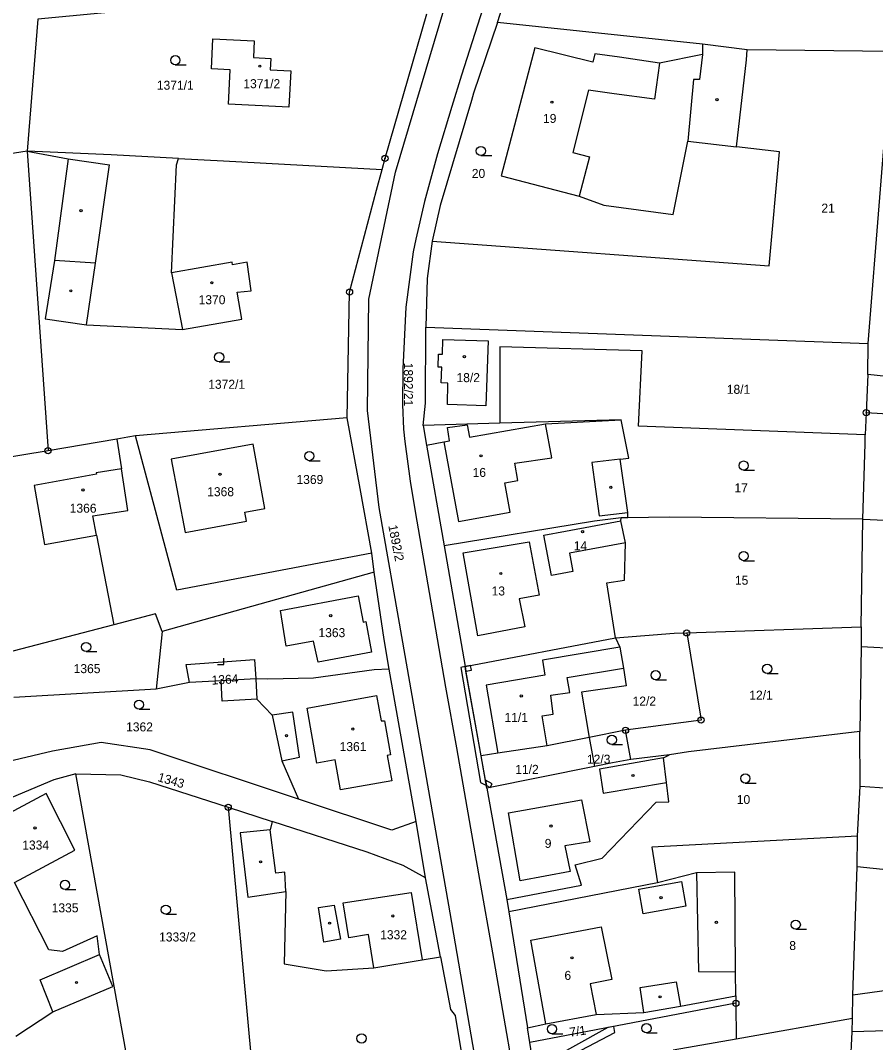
# Model space of a CAD drawing. Extents: x -587171 to -555306, y -1167727 to -1074732.
# Drawn here: x -559747.3 to -559608.7, y -1076385.1 to -1076219.5 of the extents above; entities that cross this region are included whole.
import ezdxf

# ---------------------------------------------------------------- set-up
doc = ezdxf.new("R2010")
doc.units = 0
for name, color, linetype in [('Hranice parcel', 7, 'Continuous'), ('Parcelní čísla', 7, 'Continuous'), ('Vnitřní kresba', 7, 'Continuous'), ('Věcná břemena k části', 7, 'Continuous'), ('Značky bodu BP', 7, 'Continuous'), ('Značky budov', 7, 'Continuous'), ('Značky kultur', 7, 'Continuous')]:
    doc.layers.add(name, color=color, linetype=linetype)

msp = doc.modelspace()

# ---------------------------------------------------------------- linework, layer by layer
at = {"layer": 'Hranice parcel'}
for p, q in [((-559669.97, -1076219.81), (-559666.56, -1076209.16)), ((-559688.2, -1076241.83), (-559681.43, -1076218.42)), ((-559636.74, -1076223.34), (-559669.97, -1076219.81)), ((-559629.52, -1076224.24), (-559636.74, -1076223.34)), ((-559606.11, -1076224.52), (-559629.52, -1076224.24)), ((-559609.89, -1076271.82), (-559606.11, -1076224.52)), ((-559746.19, -1076240.66), (-559774.92, -1076245.29)), ((-559746.19, -1076240.66), (-559742.81, -1076289.2)), ((-559721.97, -1076242.88), (-559721.67, -1076241.85)), ((-559688.69, -1076243.66), (-559688.2, -1076241.83)), ((-559689.57, -1076246.99), (-559688.69, -1076243.66)), ((-559681.61, -1076269.19), (-559609.89, -1076271.82)), ((-559609.99, -1076276.84), (-559609.89, -1076271.82)), ((-559609.99, -1076276.84), (-559610.23, -1076283.04)), ((-559524.17, -1076286.21), (-559609.99, -1076276.84)), ((-559610.23, -1076283.04), (-559610.37, -1076286.62)), ((-559525.24, -1076288.45), (-559610.23, -1076283.04)), ((-559694.32, -1076283.88), (-559728.64, -1076286.81)), ((-559669.62, -1076284.73), (-559682.03, -1076285.09)), ((-559731.68, -1076287.32), (-559742.81, -1076289.2)), ((-559742.81, -1076289.2), (-559761.21, -1076292.32)), ((-559649.97, -1076300.57), (-559649.96, -1076300.08)), ((-559648.87, -1076300.06), (-559649.96, -1076300.08)), ((-559649.22, -1076304.13), (-559649.97, -1076300.57)), ((-559611.07, -1076317.75), (-559610.75, -1076300.3)), ((-559610.75, -1076300.3), (-559532.59, -1076303.73)), ((-559678.62, -1076304.6), (-559675.24, -1076324.16)), ((-559689.97, -1076308.89), (-559690.36, -1076305.79)), ((-559689.97, -1076308.89), (-559724.34, -1076318.46)), ((-559732.13, -1076317.38), (-559751.67, -1076322.49)), ((-559639.31, -1076318.71), (-559611.07, -1076317.75)), ((-559611.07, -1076317.75), (-559611.03, -1076320.97)), ((-559724.34, -1076318.46), (-559725.3, -1076327.83)), ((-559675.24, -1076324.16), (-559650.83, -1076319.51)), ((-559611.03, -1076320.97), (-559611.27, -1076334.66)), ((-559542.75, -1076324.48), (-559611.03, -1076320.97)), ((-559683.14, -1076349.27), (-559687.53, -1076324.57)), ((-559672.64, -1076338.64), (-559675.24, -1076324.16)), ((-559725.3, -1076327.83), (-559748.34, -1076329.2)), ((-559719.91, -1076326.76), (-559725.3, -1076327.83)), ((-559649.23, -1076334.49), (-559655.1, -1076335.65)), ((-559648.37, -1076339.21), (-559649.23, -1076334.49)), ((-559611.22, -1076343.53), (-559611.27, -1076334.66)), ((-559655.1, -1076335.65), (-559654.28, -1076340.35)), ((-559671.7, -1076343.88), (-559672.64, -1076338.64)), ((-559642.13, -1076338.47), (-559648.37, -1076339.21)), ((-559730.08, -1076387.01), (-559738.33, -1076341.52)), ((-559654.28, -1076340.35), (-559671.7, -1076343.88)), ((-559671.7, -1076343.88), (-559668.49, -1076361.9)), ((-559611.62, -1076351.63), (-559611.22, -1076343.53)), ((-559611.22, -1076343.53), (-559553.95, -1076347.35)), ((-559713.61, -1076346.96), (-559709.16, -1076395.49)), ((-559713.61, -1076346.96), (-559706.47, -1076349.27)), ((-559681.64, -1076358.38), (-559683.14, -1076349.27)), ((-559611.68, -1076356.63), (-559611.62, -1076351.63)), ((-559612.37, -1076377.39), (-559611.68, -1076356.63)), ((-559596.39, -1076358.13), (-559611.68, -1076356.63)), ((-559679.2, -1076371.2), (-559681.64, -1076358.38)), ((-559644.06, -1076359.22), (-559668.13, -1076363.91)), ((-559668.49, -1076361.9), (-559668.13, -1076363.91)), ((-559668.13, -1076363.91), (-559665.12, -1076382.68)), ((-559682.16, -1076371.7), (-559679.2, -1076371.2)), ((-559600.56, -1076375.8), (-559612.37, -1076377.39)), ((-559631.36, -1076377.5), (-559631.35, -1076378.72)), ((-559612.46, -1076381.18), (-559612.37, -1076377.39)), ((-559631.35, -1076378.72), (-559664.74, -1076385.04)), ((-559631.35, -1076378.72), (-559631.29, -1076384.51)), ((-559612.46, -1076381.18), (-559631.29, -1076384.51)), ((-559612.51, -1076383.33), (-559612.46, -1076381.18)), ((-559664.74, -1076385.04), (-559665.12, -1076382.68)), ((-559631.29, -1076384.51), (-559641.49, -1076386.31)), ((-559613.69, -1076407.52), (-559612.51, -1076383.33)), ((-559602.27, -1076383.08), (-559612.51, -1076383.33)), ((-559663.9, -1076390.27), (-559664.74, -1076385.04))]:
    msp.add_line(p, q, dxfattribs=at)
for points in [[(-559670.6, -1076212.13), (-559675.79, -1076228.36), (-559677.4, -1076233.42), (-559679.72, -1076241.09), (-559681.8, -1076248.81), (-559683.23, -1076254.95), (-559683.64, -1076256.99), (-559684.85, -1076265.92), (-559685.34, -1076275.96), (-559685.36, -1076281.72), (-559685.2, -1076285.73), (-559685.01, -1076287.72), (-559684.15, -1076294.13), (-559683.32, -1076299.07), (-559680, -1076318.08), (-559678.38, -1076327.51), (-559676.63, -1076337.35), (-559674.34, -1076350.35), (-559672.89, -1076358.68), (-559670.79, -1076370.56), (-559668.73, -1076382.34), (-559667.79, -1076387.64)], [(-559723.95, -1076217.33), (-559744.45, -1076219.3), (-559746.19, -1076240.66)], [(-559669.97, -1076219.81), (-559673.87, -1076231.26), (-559674.19, -1076232.44), (-559679.29, -1076249.47), (-559680.58, -1076255.26)], [(-559716.34, -1076227.34), (-559716.09, -1076222.46), (-559709.41, -1076222.81), (-559709.54, -1076225.52), (-559706.72, -1076225.66), (-559706.8, -1076227.47), (-559703.48, -1076227.64), (-559703.77, -1076233.57), (-559713.58, -1076233.06), (-559713.29, -1076227.5), (-559716.34, -1076227.34)], [(-559636.74, -1076223.34), (-559636.74, -1076225.03), (-559643.7, -1076226.39), (-559650.23, -1076225.46), (-559654.21, -1076224.89), (-559654.53, -1076226.23), (-559663.93, -1076223.92), (-559669.38, -1076244.67), (-559656.76, -1076247.97), (-559652.74, -1076249.42), (-559641.52, -1076250.94), (-559639.14, -1076239.07), (-559631.27, -1076239.97)], [(-559631.27, -1076239.97), (-559629.65, -1076225.88), (-559629.52, -1076224.24)], [(-559680.58, -1076255.26), (-559625.94, -1076259.26), (-559624.26, -1076240.77), (-559631.27, -1076239.97)], [(-559721.67, -1076241.85), (-559732.61, -1076241.25), (-559746.19, -1076240.66)], [(-559746.19, -1076240.66), (-559739.57, -1076241.9), (-559741.74, -1076258.38), (-559743.29, -1076267.85), (-559736.59, -1076268.78), (-559721.03, -1076269.54), (-559711.4, -1076267.91), (-559712.16, -1076263.53), (-559709.91, -1076263.3), (-559710.52, -1076258.68), (-559712.92, -1076259.1), (-559713, -1076258.66), (-559722.83, -1076260.38), (-559721.97, -1076242.88)], [(-559721.67, -1076241.85), (-559714.39, -1076242.25), (-559688.69, -1076243.66)], [(-559694.32, -1076283.88), (-559693.95, -1076263.51), (-559689.57, -1076246.99)], [(-559680.58, -1076255.26), (-559681.38, -1076261.32), (-559681.61, -1076269.19)], [(-559682.03, -1076285.09), (-559681.62, -1076281.5), (-559681.61, -1076269.19)], [(-559678.83, -1076271.16), (-559671.5, -1076271.41), (-559671.86, -1076281.94), (-559678.09, -1076281.71), (-559678.01, -1076278.24), (-559679.09, -1076278.19), (-559679.01, -1076275.67), (-559679.6, -1076275.64), (-559679.52, -1076273.54), (-559678.91, -1076273.56), (-559678.83, -1076271.16)], [(-559610.37, -1076286.62), (-559647.15, -1076285.23), (-559646.51, -1076273.04), (-559669.61, -1076272.38), (-559669.62, -1076284.73)], [(-559690.36, -1076305.79), (-559692.23, -1076295.31), (-559694.32, -1076283.88)], [(-559682.03, -1076285.09), (-559681.46, -1076288.31), (-559678.62, -1076304.6)], [(-559648.87, -1076300.06), (-559648.87, -1076299.21), (-559650.12, -1076290.59), (-559648.68, -1076290.43), (-559649.02, -1076288.76), (-559649.93, -1076284.17), (-559669.62, -1076284.73)], [(-559728.64, -1076286.81), (-559729.87, -1076287), (-559731.68, -1076287.32)], [(-559690.36, -1076305.79), (-559721.93, -1076311.8), (-559728.64, -1076286.81)], [(-559610.75, -1076300.3), (-559610.42, -1076288.01), (-559610.37, -1076286.62)], [(-559731.68, -1076287.32), (-559730.93, -1076292.12), (-559735.02, -1076292.76), (-559734.98, -1076293.02), (-559745.06, -1076294.85), (-559743.38, -1076304.37), (-559734.96, -1076302.86), (-559732.13, -1076317.38)], [(-559720.57, -1076302.43), (-559710.66, -1076300.61), (-559710.93, -1076299.17), (-559707.66, -1076298.56), (-559709.55, -1076288.14), (-559722.85, -1076290.57), (-559720.57, -1076302.43)], [(-559649.96, -1076300.08), (-559654.24, -1076300.62), (-559678.62, -1076304.6)], [(-559610.75, -1076300.3), (-559642.18, -1076299.97), (-559648.87, -1076300.06)], [(-559649.22, -1076304.13), (-559658.29, -1076305.82), (-559657.75, -1076308.74), (-559661.2, -1076309.4), (-559662.45, -1076302.87), (-559658.98, -1076302.23), (-559649.97, -1076300.57)], [(-559650.83, -1076319.51), (-559652.28, -1076310.6), (-559649.4, -1076310.19), (-559649.22, -1076304.13)], [(-559687.53, -1076324.57), (-559688.36, -1076319.79), (-559689.97, -1076308.89)], [(-559724.34, -1076318.46), (-559725.39, -1076315.62), (-559732.13, -1076317.38)], [(-559650.83, -1076319.51), (-559650.17, -1076321.02), (-559649.56, -1076324.43), (-559649.1, -1076327.27), (-559656.38, -1076328.32), (-559655.1, -1076335.65)], [(-559650.83, -1076319.51), (-559641.35, -1076318.78), (-559639.31, -1076318.71)], [(-559639.31, -1076318.71), (-559636.99, -1076332.84), (-559649.23, -1076334.49)], [(-559719.91, -1076326.76), (-559720.42, -1076323.83), (-559709.34, -1076323.02), (-559709.14, -1076326.13)], [(-559687.53, -1076324.57), (-559689.95, -1076324.68), (-559699.8, -1076326.03), (-559707.17, -1076326.23), (-559709.14, -1076326.13)], [(-559709.14, -1076326.13), (-559714.77, -1076326.46), (-559719.91, -1076326.76)], [(-559709.14, -1076326.13), (-559708.97, -1076329.46), (-559706.49, -1076332.05), (-559704.95, -1076339.45), (-559702.24, -1076345.64)], [(-559611.27, -1076334.66), (-559639.03, -1076338), (-559642.13, -1076338.47)], [(-559702.24, -1076345.64), (-559726.29, -1076337.65), (-559734.22, -1076336.48), (-559742.09, -1076337.88), (-559756.94, -1076341.36)], [(-559655.1, -1076335.65), (-559661.91, -1076336.99), (-559669.91, -1076338.22), (-559672.64, -1076338.64)], [(-559668.49, -1076361.9), (-559656.38, -1076359.57), (-559657.4, -1076356.26), (-559653.02, -1076355.2), (-559644.24, -1076346.15), (-559642.23, -1076346.06), (-559642.58, -1076342.93), (-559643.05, -1076338.96), (-559642.13, -1076338.47)], [(-559648.37, -1076339.21), (-559651.34, -1076339.75), (-559654.28, -1076340.35)], [(-559738.33, -1076341.52), (-559741.88, -1076342.53), (-559751.79, -1076346.69)], [(-559738.33, -1076341.52), (-559731, -1076341.7), (-559726.37, -1076342.84), (-559713.61, -1076346.96)], [(-559748.02, -1076384.02), (-559742.01, -1076380.08), (-559732.34, -1076376.02), (-559734.46, -1076370.82), (-559734.83, -1076367.76), (-559740.49, -1076370.33), (-559742.68, -1076370.04), (-559748.24, -1076359.12), (-559738.45, -1076353.89), (-559743.09, -1076344.75), (-559750.71, -1076348.8), (-559751.79, -1076346.69)], [(-559683.14, -1076349.27), (-559687.08, -1076350.67), (-559702.24, -1076345.64)], [(-559706.47, -1076349.27), (-559706.8, -1076350.6), (-559711.66, -1076351.09)], [(-559681.64, -1076358.38), (-559685.26, -1076356.4), (-559691.1, -1076354.24), (-559706.47, -1076349.27)], [(-559711.66, -1076351.09), (-559710.45, -1076361.5), (-559704.29, -1076360.62)], [(-559611.62, -1076351.63), (-559644.95, -1076353.42), (-559644.06, -1076359.22)], [(-559631.36, -1076377.5), (-559631.39, -1076373.61), (-559631.53, -1076357.46), (-559637.72, -1076357.58), (-559644.06, -1076359.22)], [(-559704.29, -1076360.62), (-559704.53, -1076372.32), (-559697.73, -1076373.48)], [(-559679.2, -1076371.2), (-559677.59, -1076379.71), (-559676.86, -1076380.7), (-559670.93, -1076416.16)], [(-559697.73, -1076373.48), (-559690.04, -1076372.95), (-559682.16, -1076371.7)], [(-559665.12, -1076382.68), (-559662.15, -1076382.05), (-559653.99, -1076380.52), (-559646.25, -1076380.23), (-559640.34, -1076379.18), (-559631.36, -1076377.5)]]:
    msp.add_lwpolyline(points, dxfattribs=at)
at = {"layer": 'Vnitřní kresba'}
for p, q in [((-559686.52, -1076244.08), (-559676.92, -1076211.76)), ((-559636.74, -1076225.03), (-559637.26, -1076229.06)), ((-559643.7, -1076226.39), (-559644.51, -1076232.27)), ((-559638.23, -1076229.04), (-559639.14, -1076239.07)), ((-559637.26, -1076229.06), (-559638.23, -1076229.04)), ((-559655.24, -1076230.81), (-559657.76, -1076240.87)), ((-559651.08, -1076231.38), (-559655.24, -1076230.81)), ((-559644.51, -1076232.27), (-559651.08, -1076231.38)), ((-559739.57, -1076241.9), (-559732.83, -1076242.88)), ((-559657.76, -1076240.87), (-559655.08, -1076241.57)), ((-559655.08, -1076241.57), (-559656.76, -1076247.97)), ((-559735.14, -1076258.8), (-559732.83, -1076242.88)), ((-559690.81, -1076264.65), (-559686.52, -1076244.08)), ((-559735.14, -1076258.8), (-559741.74, -1076258.38)), ((-559736.59, -1076268.78), (-559735.14, -1076258.8)), ((-559722.83, -1076260.38), (-559721.03, -1076269.54)), ((-559691.06, -1076282.71), (-559690.81, -1076264.65)), ((-559689.16, -1076298.39), (-559691.06, -1076282.71)), ((-559678.09, -1076285.43), (-559674.87, -1076284.99)), ((-559674.87, -1076284.99), (-559674.51, -1076287.02)), ((-559674.51, -1076287.02), (-559662.21, -1076284.85)), ((-559662.21, -1076284.85), (-559649.93, -1076284.17)), ((-559661.16, -1076290.35), (-559662.21, -1076284.85)), ((-559677.78, -1076287.6), (-559678.09, -1076285.43)), ((-559681.46, -1076288.31), (-559678.67, -1076287.76)), ((-559678.67, -1076287.76), (-559677.78, -1076287.6)), ((-559678.67, -1076287.76), (-559676.28, -1076300.67)), ((-559667.19, -1076291.23), (-559661.16, -1076290.35)), ((-559666.7, -1076294.03), (-559667.19, -1076291.23)), ((-559650.12, -1076290.59), (-559654.7, -1076291.12)), ((-559654.7, -1076291.12), (-559653.51, -1076299.74)), ((-559729.87, -1076298.86), (-559730.93, -1076292.12)), ((-559668.79, -1076294.4), (-559666.7, -1076294.03)), ((-559667.93, -1076299.16), (-559668.79, -1076294.4)), ((-559685.31, -1076320.23), (-559689.16, -1076298.39)), ((-559735.58, -1076299.72), (-559729.87, -1076298.86)), ((-559734.96, -1076302.86), (-559735.58, -1076299.72)), ((-559676.28, -1076300.67), (-559667.93, -1076299.16)), ((-559653.51, -1076299.74), (-559648.87, -1076299.21)), ((-559675.52, -1076305.73), (-559664.83, -1076303.97)), ((-559664.83, -1076303.97), (-559663.21, -1076312.62)), ((-559673.18, -1076319.17), (-559675.52, -1076305.73)), ((-559705.14, -1076315.06), (-559692.55, -1076312.71)), ((-559692.55, -1076312.71), (-559691.77, -1076316.96)), ((-559663.21, -1076312.62), (-559666.44, -1076313.19)), ((-559666.44, -1076313.19), (-559665.54, -1076317.72)), ((-559704.24, -1076320.86), (-559705.14, -1076315.06)), ((-559691.77, -1076316.96), (-559691.29, -1076316.87)), ((-559691.29, -1076316.87), (-559690.38, -1076321.83)), ((-559665.54, -1076317.72), (-559673.18, -1076319.17)), ((-559699.79, -1076320.06), (-559704.24, -1076320.86)), ((-559699.05, -1076323.46), (-559699.79, -1076320.06)), ((-559677.67, -1076364.08), (-559685.31, -1076320.23)), ((-559650.17, -1076321.02), (-559662.66, -1076323.12)), ((-559690.38, -1076321.83), (-559699.05, -1076323.46)), ((-559662.66, -1076323.12), (-559662.32, -1076325.56)), ((-559658.67, -1076325.91), (-559649.56, -1076324.43)), ((-559714.57, -1076329.77), (-559714.77, -1076326.46)), ((-559662.32, -1076325.56), (-559671.79, -1076327.18)), ((-559658.28, -1076328.39), (-559658.67, -1076325.91)), ((-559671.79, -1076327.18), (-559669.91, -1076338.22)), ((-559708.97, -1076329.46), (-559714.57, -1076329.77)), ((-559700.81, -1076330.9), (-559689.57, -1076328.85)), ((-559689.57, -1076328.85), (-559688.84, -1076332.97)), ((-559661.35, -1076328.8), (-559658.28, -1076328.39)), ((-559660.95, -1076331.9), (-559661.35, -1076328.8)), ((-559703.16, -1076331.57), (-559706.49, -1076332.05)), ((-559702.06, -1076338.84), (-559703.16, -1076331.57)), ((-559699.23, -1076339.8), (-559700.81, -1076330.9)), ((-559688.84, -1076332.97), (-559688.31, -1076332.95)), ((-559688.31, -1076332.95), (-559687.31, -1076338.49)), ((-559662.76, -1076332.13), (-559660.95, -1076331.9)), ((-559661.91, -1076336.99), (-559662.76, -1076332.13)), ((-559704.95, -1076339.45), (-559702.06, -1076338.84)), ((-559696.28, -1076339.27), (-559699.23, -1076339.8)), ((-559695.4, -1076344.15), (-559696.28, -1076339.27)), ((-559687.31, -1076338.49), (-559687.83, -1076338.58)), ((-559687.83, -1076338.58), (-559687.1, -1076342.67)), ((-559643.05, -1076338.96), (-559653.44, -1076340.78)), ((-559653.44, -1076340.78), (-559652.86, -1076344.69)), ((-559687.1, -1076342.67), (-559695.4, -1076344.15)), ((-559652.86, -1076344.69), (-559642.58, -1076342.93)), ((-559668.2, -1076347.88), (-559656.39, -1076345.73)), ((-559656.39, -1076345.73), (-559655.01, -1076352.56)), ((-559666.32, -1076358.87), (-559668.2, -1076347.88)), ((-559705.9, -1076357.61), (-559706.8, -1076350.6)), ((-559655.01, -1076352.56), (-559659.05, -1076353.21)), ((-559659.05, -1076353.21), (-559658.22, -1076357.36)), ((-559704.46, -1076357.47), (-559705.9, -1076357.61)), ((-559704.29, -1076360.62), (-559704.46, -1076357.47)), ((-559658.22, -1076357.36), (-559666.32, -1076358.87)), ((-559637.72, -1076357.58), (-559637.43, -1076373.58)), ((-559647.1, -1076360.24), (-559640.15, -1076358.99)), ((-559640.15, -1076358.99), (-559639.43, -1076362.98)), ((-559695.01, -1076362.46), (-559683.98, -1076360.74)), ((-559683.98, -1076360.74), (-559682.16, -1076371.7)), ((-559646.37, -1076364.24), (-559647.1, -1076360.24)), ((-559699.01, -1076363.17), (-559696.46, -1076362.84)), ((-559696.46, -1076362.84), (-559695.43, -1076368.33)), ((-559694.07, -1076368.1), (-559695.01, -1076362.46)), ((-559639.43, -1076362.98), (-559646.37, -1076364.24)), ((-559698.12, -1076368.83), (-559699.01, -1076363.17)), ((-559669.69, -1076410.23), (-559677.67, -1076364.08)), ((-559664.57, -1076368.51), (-559653.19, -1076366.33)), ((-559653.19, -1076366.33), (-559651.46, -1076374.87)), ((-559690.87, -1076367.57), (-559694.07, -1076368.1)), ((-559690.04, -1076372.95), (-559690.87, -1076367.57)), ((-559695.43, -1076368.33), (-559698.12, -1076368.83)), ((-559662.15, -1076382.05), (-559664.57, -1076368.51)), ((-559744.11, -1076374.91), (-559734.46, -1076370.82)), ((-559637.43, -1076373.58), (-559631.39, -1076373.61)), ((-559742.01, -1076380.08), (-559744.11, -1076374.91)), ((-559651.46, -1076374.87), (-559654.96, -1076375.57)), ((-559654.96, -1076375.57), (-559653.99, -1076380.52)), ((-559646.85, -1076376.18), (-559641.04, -1076375.23)), ((-559646.25, -1076380.23), (-559646.85, -1076376.18)), ((-559641.04, -1076375.23), (-559640.34, -1076379.18))]:
    msp.add_line(p, q, dxfattribs=at)
at = {"layer": 'Věcná břemena k části'}
for points in [[(-559671.78, -1076343.44), (-559671.93, -1076342.58), (-559672.64, -1076338.64), (-559675.1, -1076324.93), (-559675.24, -1076324.16), (-559675.92, -1076324.29), (-559672.73, -1076342.96)], [(-559674.19, -1076324.73), (-559674.35, -1076323.99), (-559675.24, -1076324.16), (-559675.1, -1076324.93)], [(-559670.83, -1076343.16), (-559671.93, -1076342.58), (-559671.78, -1076343.44), (-559671.14, -1076343.77)], [(-559652.12, -1076382.65), (-559664.06, -1076389.28), (-559663.9, -1076390.27), (-559650.94, -1076383.43), (-559651.14, -1076382.47)]]:
    msp.add_lwpolyline(points, close=True, dxfattribs=at)
at = {"layer": 'Značky bodu BP'}
for centre, radius in [((-559688.2, -1076241.83), 0.5), ((-559688.2, -1076241.83), 0.0303), ((-559693.95, -1076263.51), 0.5), ((-559693.95, -1076263.51), 0.0303), ((-559610.23, -1076283.04), 0.5), ((-559610.23, -1076283.04), 0.0303), ((-559742.81, -1076289.2), 0.5), ((-559742.81, -1076289.2), 0.0303), ((-559639.31, -1076318.71), 0.5), ((-559639.31, -1076318.71), 0.0303), ((-559636.99, -1076332.84), 0.5), ((-559636.99, -1076332.84), 0.0303), ((-559649.23, -1076334.49), 0.5), ((-559649.23, -1076334.49), 0.0303), ((-559713.61, -1076346.96), 0.5), ((-559713.61, -1076346.96), 0.0303), ((-559631.35, -1076378.72), 0.5), ((-559631.35, -1076378.72), 0.0303)]:
    msp.add_circle(centre, radius, dxfattribs=at)
at = {"layer": 'Značky budov'}
for centre in [(-559708.49, -1076226.9), (-559634.41, -1076232.33), (-559661.16, -1076232.73), (-559737.47, -1076250.3), (-559716.28, -1076261.99), (-559739.12, -1076263.3), (-559675.34, -1076273.95), (-559672.64, -1076290.03), (-559714.94, -1076293.01), (-559651.6, -1076295.13), (-559737.15, -1076295.55), (-559656.19, -1076302.3), (-559669.44, -1076309.09), (-559697.01, -1076315.93), (-559666.12, -1076328.93), (-559693.41, -1076334.29), (-559704.18, -1076335.37), (-559648.03, -1076341.82), (-559661.31, -1076350), (-559744.92, -1076350.31), (-559708.37, -1076355.8), (-559643.48, -1076361.59), (-559686.94, -1076364.57), (-559697.19, -1076365.73), (-559634.51, -1076365.6), (-559657.91, -1076371.35), (-559738.21, -1076375.35), (-559643.63, -1076377.66)]:
    msp.add_circle(centre, 0.175, dxfattribs=at)
at = {"layer": 'Značky kultur'}
for p, q in [((-559722.19, -1076226.69), (-559720.44, -1076226.69)), ((-559672.67, -1076241.39), (-559670.92, -1076241.39)), ((-559715.09, -1076274.8), (-559713.34, -1076274.8)), ((-559700.47, -1076290.81), (-559698.72, -1076290.81)), ((-559630.09, -1076292.36), (-559628.34, -1076292.36)), ((-559630.09, -1076307.01), (-559628.34, -1076307.01)), ((-559736.64, -1076321.74), (-559734.89, -1076321.74)), ((-559714.33, -1076323.81), (-559714.33, -1076322.81)), ((-559715.33, -1076323.81), (-559714.33, -1076323.81)), ((-559644.35, -1076326.31), (-559642.6, -1076326.31)), ((-559626.27, -1076325.28), (-559624.52, -1076325.28)), ((-559728.07, -1076331.09), (-559726.32, -1076331.09)), ((-559651.45, -1076336.79), (-559649.7, -1076336.79)), ((-559629.82, -1076343.04), (-559628.07, -1076343.04)), ((-559740.06, -1076360.28), (-559738.31, -1076360.28)), ((-559723.72, -1076364.3), (-559721.97, -1076364.3)), ((-559621.65, -1076366.73), (-559619.9, -1076366.73)), ((-559661.15, -1076383.64), (-559659.4, -1076383.64)), ((-559645.83, -1076383.5), (-559644.08, -1076383.5))]:
    msp.add_line(p, q, dxfattribs=at)
for centre in [(-559722.19, -1076225.94), (-559672.67, -1076240.64), (-559715.09, -1076274.05), (-559700.47, -1076290.06), (-559630.09, -1076291.61), (-559630.09, -1076306.26), (-559736.64, -1076320.99), (-559644.35, -1076325.56), (-559626.27, -1076324.53), (-559728.07, -1076330.34), (-559651.45, -1076336.04), (-559629.82, -1076342.29), (-559740.06, -1076359.53), (-559723.72, -1076363.55), (-559621.65, -1076365.98), (-559661.15, -1076382.89), (-559645.83, -1076382.75), (-559692.01, -1076384.41)]:
    msp.add_circle(centre, 0.75, dxfattribs=at)

# ---------------------------------------------------------------- texts
at = {"layer": 'Parcelní čísla'}
for s, p in [('1371/2', (-559711.16, -1076230.47)), ('1371/1', (-559725.18, -1076230.72)), ('19', (-559662.6, -1076236.1)), ('20', (-559674.14, -1076245.01)), ('21', (-559617.49, -1076250.63)), ('1370', (-559718.41, -1076265.47)), ('18/2', (-559676.62, -1076278.09)), ('1372/1', (-559716.85, -1076279.17)), ('18/1', (-559632.82, -1076279.98)), ('1369', (-559702.55, -1076294.59)), ('16', (-559674.01, -1076293.45)), ('1368', (-559717.02, -1076296.57)), ('17', (-559631.58, -1076295.96)), ('1366', (-559739.3, -1076299.24)), ('14', (-559657.62, -1076305.32)), ('15', (-559631.5, -1076310.91)), ('13', (-559670.93, -1076312.65)), ('1363', (-559698.99, -1076319.4)), ('1365', (-559738.66, -1076325.23)), ('12/1', (-559629.17, -1076329.52)), ('12/2', (-559648.08, -1076330.49)), ('11/1', (-559668.84, -1076333.13)), ('1362', (-559730.16, -1076334.67)), ('1361', (-559695.56, -1076337.86)), ('12/3', (-559655.48, -1076339.9)), ('11/2', (-559667.1, -1076341.55)), ('10', (-559631.2, -1076346.43)), ('1334', (-559746.99, -1076353.81)), ('9', (-559662.32, -1076353.54)), ('1335', (-559742.22, -1076363.98)), ('1333/2', (-559724.81, -1076368.7)), ('1332', (-559688.99, -1076368.34)), ('8', (-559622.69, -1076370.09)), ('6', (-559659.13, -1076374.92))]:
    msp.add_text(s, height=1.46, dxfattribs=at).set_placement(p)
for s, rotation, p in [('1892/21', 270, (-559685.15, -1076274.94)), ('1892/2', 281, (-559687.68, -1076301.35)), ('1364', 3, (-559716.27, -1076327.1)), ('1343', 344, (-559725.15, -1076342.7)), ('7/1', 8, (-559658.22, -1076384.14))]:
    msp.add_text(s, height=1.46, rotation=rotation, dxfattribs=at).set_placement(p)

doc.saveas('drawing.dxf')
